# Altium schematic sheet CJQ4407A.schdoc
size 127 x 101 mm
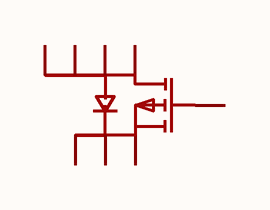
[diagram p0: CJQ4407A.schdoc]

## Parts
Q?  cjq4407a  [SOP-8_L4.9-W3.9-P1.27-LS6.0-BL]  (value not drawn)

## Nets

Not connected (* = marked no-connect by the designer): Q? 1(S) 2(S) 3(S) 4(G) 5(D) 6(D) 7(D) 8(D)

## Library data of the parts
Q? = cjq4407a: 数量:1个P沟道;漏源电压(Vdss):30V;连续漏极电流(Id):11A;导通电阻(RDS(on)):17mΩ@6V;耗散功率(Pd):2.65W;阈值电压(Vgs(th)):2.2V;; Manufacturer: CJ(江苏长电/长晶); AddInBom: yes; ModelId: 75c24a7891ee4dd6bdac16a7163ff87e; ModelName: SOP-8_L4.9-W3.9-P1.27-LS6.0-BL-1; ModelTransform: 192.913,236.22,0,0,0,0,-0.393,2.749,0; Number: 1个P沟道; Drain to Source Voltage: 30V; Current - Continuous Drain(Id): 11A; Pd - Power Dissipation: 2.65W; Gate Threshold Voltage (Vgs(th)): 2.2V; Gate Charge(Qg): 38nC@10V; Input Capacitance(Ciss): 2.015nF; Reverse Transfer Capacitance (Crss@Vds): 210pF; Type: P沟道; Output Capacitance(Coss): 277pF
